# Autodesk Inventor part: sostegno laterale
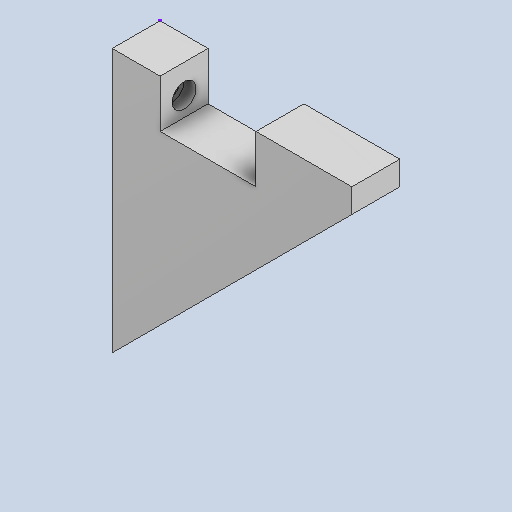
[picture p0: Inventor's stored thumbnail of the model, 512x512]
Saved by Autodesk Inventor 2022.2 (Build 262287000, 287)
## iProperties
Created: 2024-10
Part Number: sostegno laterale
Material: Alluminio 6061
Document SubType Name: Modeling
Designer: 18907419
Density: 2.7 g/cm^3
Appearance: Default
Author: 18907419
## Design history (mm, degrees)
node "Geometria corretta1"
  node "Schizzo3"
feature "Solido1"
node "Solido2"
